(* Logix 5000 project; controller L32E vendor 1 type 14 code 77 rev 13.1; software revision 13.03 *)

TASK MainTask (continuous, watchdog 500 ms) : MainProgram

MODULES
   Controller : vendor 1 type 14 code 77 (CompactLogixL32EController 0, rev 13.1)
      LocalENB : 1769-L32E Ethernet Port (CompactLogixL32Ethernet 1, rev 13.1)
      Local : CompactBus (CompactVirtualAdapter 3, rev 13.1, Input RPI 2 ms)
         DPS : 1769-MODULE (Compact 1, rev 1.1, Output RPI 2 ms)   // 1769-DPS
END_MODULES

TYPE APP_CONSTANT_PATTERN :   // Constant Values Used for DPV1 Alarm and ExtDiagData
STRUCT
   UserAlarmData : SINT[32];   // Constants for Alarm Data
END_STRUCT
END_TYPE

TYPE APP_DPV1_PROG_CONTROL :   // Program Control Bits
STRUCT
   MainInitDone : BOOL;   // Main Initialization Complete
   Dpv1ReadRespInProgress : BOOL;   // DPV1 Read Response in Progress
   Dpv1WriteRespInProgress : BOOL;   // DPV1 Write Response in Progress
   Dpv1AlarmReqSend : BOOL;   // DPV1 Alarm Request Flag
   Dpv1AlarmReqInProgress : BOOL;   // DPV1 Alarm Request in Progress
   DpsDiagReqSend : BOOL;   // DPS Diagnostics Request Flag
   DpsDiagReqInProgress : BOOL;   // DPS Diagnostic Request in Progress
   Reserved0 : BOOL;   // Reserved
   Reserved1 : BOOL;   // Reserved
   Reserved2 : BOOL;   // Reserved
   Reserved3 : BOOL;   // Reserved
   Reserved4 : BOOL;   // Reserved
   Reserved5 : BOOL;   // Reserved
   Reserved6 : BOOL;   // Reserved
   Reserved7 : BOOL;   // Reserved
   Reserved8 : BOOL;   // Reserved
   DPV1RWIndCnt : SINT;   // DPV1 R/W Indication Counter
END_STRUCT
END_TYPE

TYPE APP_DPV1_STAT_COUNTER :   // DPV1 Status Counter
STRUCT
   NumReadWrite : DINT;   // Number of DPV1 Read Write Response Sent
   ReadRespPos : DINT;   // Number of DPV1 Read Response Successful
   ReadRespNeg : DINT;   // Number of DPV1 Read Response Failed
   WriteRespPos : DINT;   // Number of DPV1 Write Response Successful
   WriteRespNeg : DINT;   // Number of DPV1 Write Response Failed
   NumAlarmRequest : DINT;   // Number of DPV1 Alarm Requests sent
   AlarmRequestPos : DINT;   // Number of DPV1 Alarm Requests Successful
   AlarmRequestNeg : DINT;   // Number of DPV1 Alarm Requests Failed
   NumDiagReq : DINT;   // Number of Diagnostic Reports Sent
   DiagReqPos : DINT;   // Number of Diagnostic Report Successful
   DiagReqNeg : DINT;   // Number of Diagnostic Report Failed
END_STRUCT
END_TYPE

TYPE DPS_DEV_COMMAND_REGISTER :   // Device Command Register
STRUCT
   Reserved0 : BOOL;   // Reserved
   Reserved1 : BOOL;   // Reserved
   Reserved2 : BOOL;   // Reserved
   Reserved3 : BOOL;   // Reserved
   Reserved4 : BOOL;   // Reserved
   NRdy : BOOL;   // Application Not Ready
   Init : BOOL;   // Init ( Warm boot )
   Reset : BOOL;   // Reset ( Cold boot )
   Reserved5 : SINT;   // Reserved
   Reserved6 : SINT;   // Reserved
   ExtStaSelect : SINT;   // Extra Status Select
END_STRUCT
END_TYPE

TYPE DPS_DEV_STATUS_REGISTER :   // Device Status Register
STRUCT
   Reserved0 : BOOL;   // Reserved
   Reserved1 : BOOL;   // Reserved
   Reserved2 : BOOL;   // Reserved
   Reserved3 : BOOL;   // Reserved
   Reserved4 : BOOL;   // Reserved
   Com : BOOL;   // Communication
   Run : BOOL;   // Running
   Rdy : BOOL;   // Ready
   Reserved5 : SINT;   // Reserved
   Reserved6 : SINT;   // Reserved
   Reserved7 : SINT;   // Reserved
END_STRUCT
END_TYPE

TYPE DPS_DIAGNOSTIC_CONFIRM :   // DPS Diagnostics Confirmation
STRUCT
   Reserved1 : INT;   // Reserved
   Reserved2 : INT;   // Reserved
   Answer : SINT;   // Answer of Diag Req
   Failure : SINT;   // Failure
   Reserved4 : INT;   // Reserved
   Reserved5 : INT;   // Reserved
   Reserved6 : INT;   // Reserved
   Reserved7 : SINT;   // Reserved
   ExtDiagDataCnt : SINT;   // Extended Diagnostics Data Count
   Mode : SINT;   // Mode
   Function : SINT;   // Function
END_STRUCT
END_TYPE

TYPE DPS_DIAGNOSTIC_REQUEST :   // DPS Diagnostics Request
STRUCT
   Reserved1 : INT;   // Reserved
   Reserved2 : INT;   // Reserved
   Reserved3 : INT;   // Reserved
   Command : SINT;   // Command for Diag Req = 24
   Reserved4 : SINT;   // Reserved
   Reserved5 : INT;   // Reserved
   Reserved6 : INT;   // Reserved
   Reserved7 : SINT;   // Reserved
   ExtDiagDataCnt : SINT;   // Number of ext. diag data
   Mode : SINT;   // Diag mode: (0 = default, 1 = suppress Ext.DiagBit)
   Function : SINT;   // Send diag once (fix 18)
   DiagData : SINT[32];   // Extended diag data (format see PROFIBUS Norm)
END_STRUCT
END_TYPE

TYPE DPS_DPV1C1_ALARM_CONFIRM :   // DPV1 Alarm Confirmation
STRUCT
   Reserved1 : INT;   // Reserved
   Reserved2 : INT;   // Reserved
   Answer : SINT;   // DPV1 Alarm Answer Flag
   Failure : SINT;   // DPV1 Alarm Failure
   Reserved3 : INT;   // Reserved
   Reserved4 : INT;   // Reserved
   SlotNumber : INT;   // DPV1 Alarm Slot Number
   SequenceNumber : SINT;   // DPV1 Alarm Sequence Number
   DataCnt : SINT;   // DPV1 Alarm Data Count
   AlarmType : SINT;   // DPV1 Alarm Type
   Specifier : SINT;   // DPV1 Alarm Specifier
END_STRUCT
END_TYPE

TYPE DPS_DPV1C1_ALARM_REQUEST :   // DPV1 Alarm Request
STRUCT
   Reserved1 : INT;   // Reserved
   Reserved2 : INT;   // Reserved
   Reserved3 : INT;   // Reserved
   Command : SINT;   // DPV1 Alarm Command
   Reserved4 : SINT;   // Reserved
   Reserved5 : INT;   // Reserved
   SlotNumber : INT;   // DPV1 Alarm Slot Number
   SequenceNumber : SINT;   // DPV1 Alarm Sequence Number
   DataCnt : SINT;   // DPV1 Alarm Data Count
   AlarmType : SINT;   // DPV1 Alarm Type
   Specifier : SINT;   // DPV1 Alarm Specifier
   AlarmData : SINT[28];   // DPV1 Alarm Data Array
END_STRUCT
END_TYPE

TYPE DPS_DPV1C1_RW_INDICATION :   // DPV1 C1 Read/Write Indication
STRUCT
   ReadReq : BOOL;   // Indicates a Read request
   WriteReq : BOOL;   // Indicates a Write request
   Reserved2 : BOOL;   // Reserved
   Reserved3 : BOOL;   // Reserved
   Reserved4 : BOOL;   // Reserved
   Reserved5 : BOOL;   // Reserved
   Reserved6 : BOOL;   // Reserved
   Reserved7 : BOOL;   // Reserved
   RwCnt : SINT;   // ReadWrite indication counter
   MaAdr : SINT;   // Address of reqesting master
   Slot : SINT;   // Requested Slot Number
   Index : SINT;   // Requested Index
   DataLen : SINT;   // Requested Data Length
   Reserved8 : SINT;   // Reserved
   Reserved9 : SINT;   // Reserved
END_STRUCT
END_TYPE

TYPE DPS_DPV1C1_RW_RESP_CONFIRM :   // DPV1 Class 1 Read/Write Confirmation
STRUCT
   Reserved1 : INT;   // Reserved
   Reserved2 : INT;   // Reserved
   Answer : SINT;   // DPV1 R/W Answer
   Failure : SINT;   // DPV1 R/W Failure
   Reserved3 : INT;   // Reserved
   RwResp : SINT;   // Read Resp (=1) or Write Resp (=2)
   Reserved4 : SINT;   // Reserved
   MaAdr : SINT;   // Reply of reqesting Master Address
   Slot : SINT;   // Reply of requested Slot Number
   Index : SINT;   // Reply of requested Index
   DataLen : SINT;   // Number of requested data
   ErrCode1 : SINT;   // Reply of Error code 1 according to DPV1
   ErrCode2 : SINT;   // Reply of Error code 2 according to DPV1
   RWRespData : SINT[240];   // DPV1 Write data
END_STRUCT
END_TYPE

TYPE DPS_DPV1C1_RW_RESP_REQUEST :   // DPV1 Class 1 Read/Write Response Request
STRUCT
   Reserved1 : INT;   // Reserved
   Reserved2 : INT;   // Reserved
   Reserved3 : INT;   // Reserved
   Command : SINT;   // DPV1 ReadWrite Resp. Request (=17)
   Reserved4 : SINT;   // Reserved
   RwResp : SINT;   // Read Resp (=1) or Write Resp (=2)
   Reserved5 : SINT;   // Reserved
   MaAdr : SINT;   // Reply of reqesting Master Address
   Slot : SINT;   // Reply of requested Slot Number
   Index : SINT;   // Reply of requested Index
   DataLen : SINT;   // Reply of requested number of data
   ErrCode1 : SINT;   // Error code 1 according to DPV1
   ErrCode2 : SINT;   // Error code 2 according to DPV1
   RWRespData : SINT[240];   // DPV1 Read response data
END_STRUCT
END_TYPE

TYPE DPS_FW_REVISION :   // Firmware Major/Minor Revision
STRUCT
   FwMinor : SINT;   // Firmware Minor Revison
   FwMajor : SINT;   // Firmware Major Revison
   Reserved : INT;   // Reserved
END_STRUCT
END_TYPE

TYPE DPS_INPUT_ARRAY :   // DPS Input Array
STRUCT
   DevStaReg : DPS_DEV_STATUS_REGISTER;   // Device Status Registers
   FwRev : DPS_FW_REVISION;   // Firmware Revision
   StaField : DPS_STATUS_FIELD;   // DPS Status Registers
   PBOutputData : SINT[380];   // PROFIBUS Output Data from Matser
END_STRUCT
END_TYPE

TYPE DPS_OUTPUT_ARRAY :   // DPS Output Array
STRUCT
   DevCmdReg : DPS_DEV_COMMAND_REGISTER;   // Device Command Register
   PBInputData : SINT[244];   // PROFIBIBUS Input Data for Master
END_STRUCT
END_TYPE

TYPE DPS_STATUS_FIELD :   // DPS Status Field
STRUCT
   ExtStaSelect : INT;   // Extended Status Select
   ExtStaLen : INT;   // Extended Status Length
   Baudrate : INT;   // Slave Baudrate
   Busaddress : SINT;   // Slave Bus Address
   UserFlags : SINT;   // User Flags
   Ident : INT;   // Slave Ident Number
   TaskState : INT;   // Slave Task State
   InputDataLen : INT;   // Slave Input Data Length
   OutputDataLen : INT;   // Slave Output Data Length
   ErrorCount : INT;   // Slave Error Count
   LastError : SINT;   // Slave Last Error
   Pad : SINT;   // Reserved
   WatchdogTime : INT;   // Slave Watchdog Time
   IrqCounter : INT;   // Slave Interrupt Counter
   C1Ind : DPS_DPV1C1_RW_INDICATION;   // DPV1 Class 1 Indication Registers
   ExtStatusInfo : SINT[96];   // Extened Status Information
END_STRUCT
END_TYPE

VAR_GLOBAL   (* controller tags *)
   AppConstPattern : APP_CONSTANT_PATTERN := (UserAlarmData[0] := 'M', UserAlarmData[1] := 'A', UserAlarmData[2] := 'Y', UserAlarmData[3] := 'D', UserAlarmData[4] := 'A', UserAlarmData[5] := 'Y', UserAlarmData[6] := ',', UserAlarmData[7] := ' ', UserAlarmData[8] := 'M', UserAlarmData[9] := 'A', UserAlarmData[10] := 'Y', UserAlarmData[11] := 'D', UserAlarmData[12] := 'A', UserAlarmData[13] := 'Y');
   AppCtrl : APP_DPV1_PROG_CONTROL;
   AppStatCnt : APP_DPV1_STAT_COUNTER;
   DiagCnf : DPS_DIAGNOSTIC_CONFIRM;
   DiagReq : DPS_DIAGNOSTIC_REQUEST;
   DiagReqMsg : MESSAGE;
        MessageParameters(ServiceCode := 16#0064, LocalElement := DiagReq, DestinationTag := DiagCnf, ...)
   DpsInputArray : DPS_INPUT_ARRAY;
   DpsOutputArray : DPS_OUTPUT_ARRAY;
   Dpv1AlarmCnf : DPS_DPV1C1_ALARM_CONFIRM;
   Dpv1AlarmMsg : MESSAGE;
        MessageParameters(ServiceCode := 16#0064, LocalElement := Dpv1AlarmReq, DestinationTag := Dpv1AlarmCnf, ...)
   Dpv1AlarmReq : DPS_DPV1C1_ALARM_REQUEST := (DataCnt := 15);
   DPV1RWDataBuffer : SINT[240];   // Buffer for DPV1 Data
   Dpv1RWMsg : MESSAGE;
        MessageParameters(ServiceCode := 16#0064, LocalElement := Dpv1RWRespReq, DestinationTag := Dpv1RWRespCnf, ...)
   Dpv1RWRespCnf : DPS_DPV1C1_RW_RESP_CONFIRM;
   Dpv1RWRespReq : DPS_DPV1C1_RW_RESP_REQUEST;
END_VAR

PROGRAM MainProgram   (* routine attr 65 MainRoutine *)

ROUTINE Diagnostic_Req   (* ladder *)
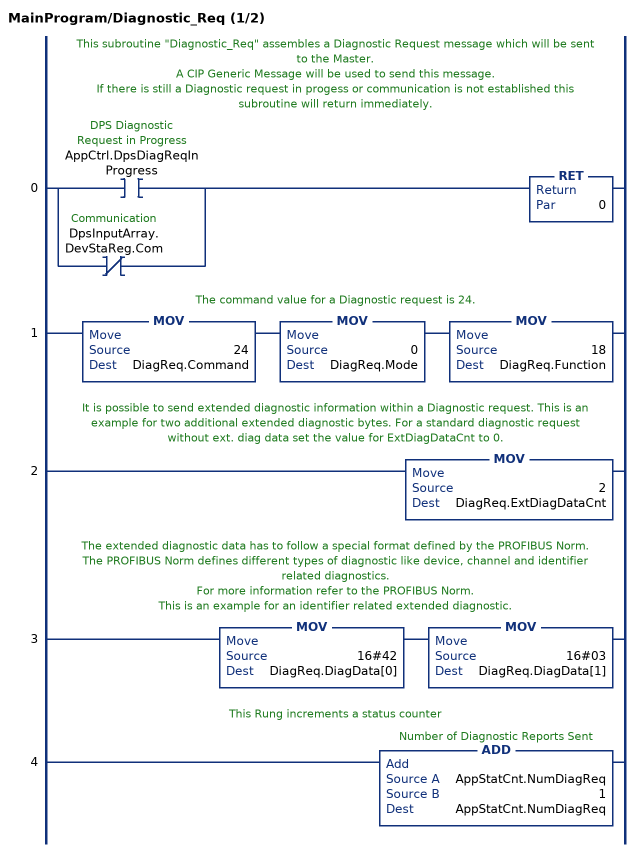
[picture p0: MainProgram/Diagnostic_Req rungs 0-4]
   // This subroutine "Diagnostic_Req" assembles a Diagnostic Request message which will be sent to the Master.
   // A CIP Generic Message will be used to send this message.
   // If there is still a Diagnostic request in progess or communication is not established this subroutine will return immediately.
   0: [XIC(AppCtrl.DpsDiagReqInProgress) ,XIO(DpsInputArray.DevStaReg.Com) ]RET(0);
   // The command value for a Diagnostic request is 24.
   1: MOV(24,DiagReq.Command)MOV(0,DiagReq.Mode)MOV(18,DiagReq.Function);
   // It is possible to send extended diagnostic information within a Diagnostic request. This is an example for two additional extended diagnostic bytes. For a standard diagnostic request without ext. diag data set the value for ExtDiagDataCnt to 0.
   2: MOV(2,DiagReq.ExtDiagDataCnt);
   // The extended diagnostic data has to follow a special format defined by the PROFIBUS Norm. The PROFIBUS Norm defines different types of diagnostic like device, channel and identifier related diagnostics.
   // For more information refer to the PROFIBUS Norm.
   // This is an example for an identifier related extended diagnostic.
   3: MOV(16#42,DiagReq.DiagData[0])MOV(16#03,DiagReq.DiagData[1]);
   // This Rung increments a status counter
   4: ADD(AppStatCnt.NumDiagReq,1,AppStatCnt.NumDiagReq);
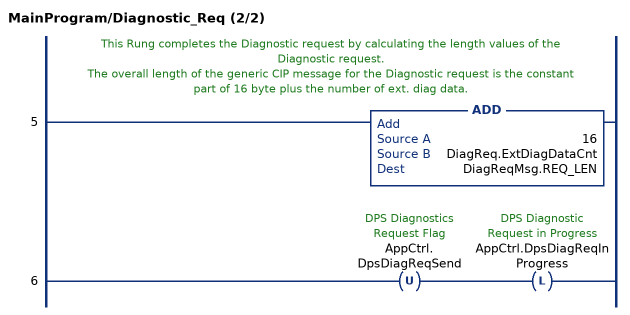
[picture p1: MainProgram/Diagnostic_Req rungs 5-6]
   // This Rung completes the Diagnostic request by calculating the length values of the Diagnostic request.
   // The overall length of the generic CIP message for the Diagnostic request is the constant part of 16 byte plus the number of ext. diag data.
   5: ADD(16,DiagReq.ExtDiagDataCnt,DiagReqMsg.REQ_LEN);
   6: OTU(AppCtrl.DpsDiagReqSend)OTL(AppCtrl.DpsDiagReqInProgress);
END_ROUTINE

ROUTINE Diagnostic_Req_Progress   (* ladder *)
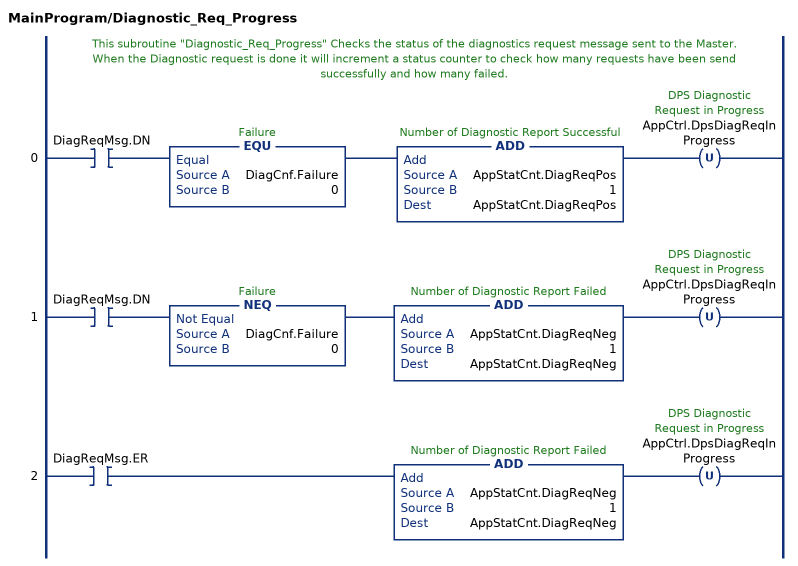
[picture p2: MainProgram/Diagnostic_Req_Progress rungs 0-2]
   // This subroutine "Diagnostic_Req_Progress" Checks the status of the diagnostics request message sent to the Master.
   // When the Diagnostic request is done it will increment a status counter to check how many requests have been send successfully and how many failed.
   0: XIC(DiagReqMsg.DN)EQU(DiagCnf.Failure,0)ADD(AppStatCnt.DiagReqPos,1,AppStatCnt.DiagReqPos)OTU(AppCtrl.DpsDiagReqInProgress);
   1: XIC(DiagReqMsg.DN)NEQ(DiagCnf.Failure,0)ADD(AppStatCnt.DiagReqNeg,1,AppStatCnt.DiagReqNeg)OTU(AppCtrl.DpsDiagReqInProgress);
   2: XIC(DiagReqMsg.ER)ADD(AppStatCnt.DiagReqNeg,1,AppStatCnt.DiagReqNeg)OTU(AppCtrl.DpsDiagReqInProgress);
END_ROUTINE

ROUTINE DPV1C1_Alarm_Req   (* ladder *)
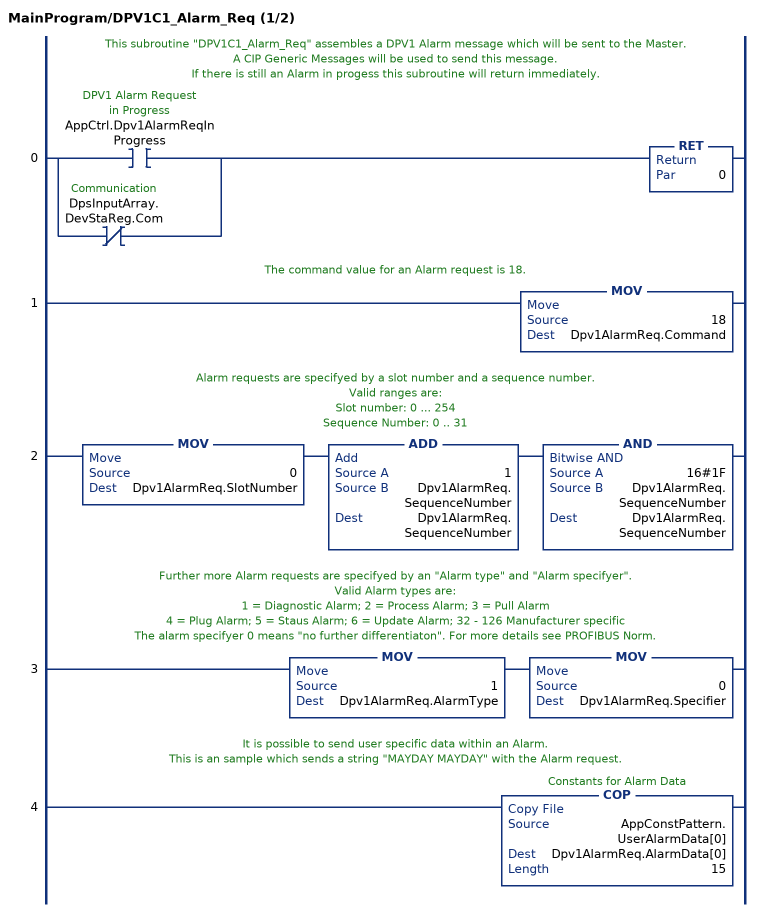
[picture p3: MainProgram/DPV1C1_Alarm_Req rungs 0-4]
   // This subroutine "DPV1C1_Alarm_Req" assembles a DPV1 Alarm message which will be sent to the Master.
   // A CIP Generic Messages will be used to send this message.
   // If there is still an Alarm in progess this subroutine will return immediately.
   0: [XIC(AppCtrl.Dpv1AlarmReqInProgress) ,XIO(DpsInputArray.DevStaReg.Com) ]RET(0);
   // The command value for an Alarm request is 18.
   1: MOV(18,Dpv1AlarmReq.Command);
   // Alarm requests are specifyed by a slot number and a sequence number.
   // Valid ranges are:
   // Slot number: 0 ... 254
   // Sequence Number: 0 .. 31
   2: MOV(0,Dpv1AlarmReq.SlotNumber)ADD(1,Dpv1AlarmReq.SequenceNumber,Dpv1AlarmReq.SequenceNumber)AND(16#1F,Dpv1AlarmReq.SequenceNumber,Dpv1AlarmReq.SequenceNumber);
   // Further more Alarm requests are specifyed by an "Alarm type" and "Alarm specifyer".
   // Valid Alarm types are:
   // 1 = Diagnostic Alarm; 2 = Process Alarm; 3 = Pull Alarm
   // 4 = Plug Alarm; 5 = Staus Alarm; 6 = Update Alarm; 32 - 126 Manufacturer specific
   // The alarm specifyer 0 means "no further differentiaton". For more details see PROFIBUS Norm.
   3: MOV(1,Dpv1AlarmReq.AlarmType)MOV(0,Dpv1AlarmReq.Specifier);
   // It is possible to send user specific data within an Alarm.
   // This is an sample which sends a string "MAYDAY MAYDAY" with the Alarm request.
   4: COP(AppConstPattern.UserAlarmData[0],Dpv1AlarmReq.AlarmData[0],15);
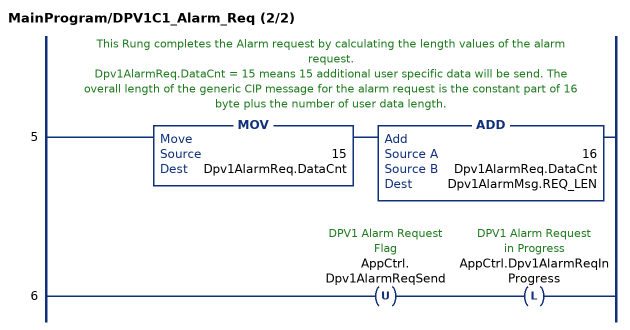
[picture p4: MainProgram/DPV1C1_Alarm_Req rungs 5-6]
   // This Rung completes the Alarm request by calculating the length values of the alarm request.
   // Dpv1AlarmReq.DataCnt = 15 means 15 additional user specific data will be send. The overall length of the generic CIP message for the alarm request is the constant part of 16 byte plus the number of user data length.
   5: MOV(15,Dpv1AlarmReq.DataCnt)ADD(16,Dpv1AlarmReq.DataCnt,Dpv1AlarmMsg.REQ_LEN);
   6: OTU(AppCtrl.Dpv1AlarmReqSend)OTL(AppCtrl.Dpv1AlarmReqInProgress);
END_ROUTINE

ROUTINE DPV1C1_Alarm_Req_Progress   (* ladder *)
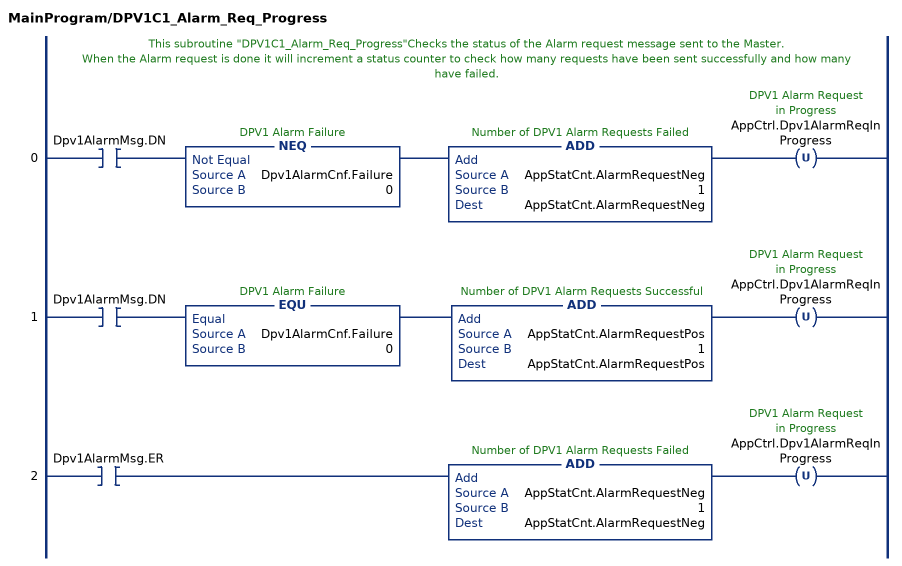
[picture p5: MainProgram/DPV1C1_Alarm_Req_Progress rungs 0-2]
   // This subroutine "DPV1C1_Alarm_Req_Progress"Checks the status of the Alarm request message sent to the Master.
   // When the Alarm request is done it will increment a status counter to check how many requests have been sent successfully and how many have failed.
   0: XIC(Dpv1AlarmMsg.DN)NEQ(Dpv1AlarmCnf.Failure,0)ADD(AppStatCnt.AlarmRequestNeg,1,AppStatCnt.AlarmRequestNeg)OTU(AppCtrl.Dpv1AlarmReqInProgress);
   1: XIC(Dpv1AlarmMsg.DN)EQU(Dpv1AlarmCnf.Failure,0)ADD(AppStatCnt.AlarmRequestPos,1,AppStatCnt.AlarmRequestPos)OTU(AppCtrl.Dpv1AlarmReqInProgress);
   2: XIC(Dpv1AlarmMsg.ER)ADD(AppStatCnt.AlarmRequestNeg,1,AppStatCnt.AlarmRequestNeg)OTU(AppCtrl.Dpv1AlarmReqInProgress);
END_ROUTINE

ROUTINE DPV1C1_Progress   (* ladder *)
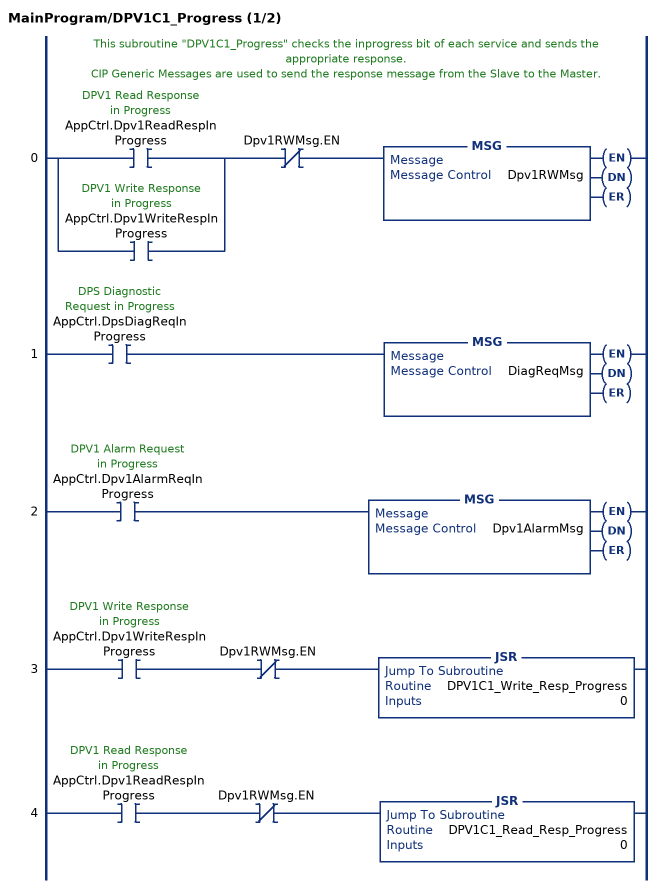
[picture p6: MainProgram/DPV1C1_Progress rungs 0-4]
   // This subroutine "DPV1C1_Progress" checks the inprogress bit of each service and sends the appropriate response.
   // CIP Generic Messages are used to send the response message from the Slave to the Master.
   0: [XIC(AppCtrl.Dpv1ReadRespInProgress) ,XIC(AppCtrl.Dpv1WriteRespInProgress) ]XIO(Dpv1RWMsg.EN)MSG(Dpv1RWMsg);
   1: XIC(AppCtrl.DpsDiagReqInProgress)MSG(DiagReqMsg);
   2: XIC(AppCtrl.Dpv1AlarmReqInProgress)MSG(Dpv1AlarmMsg);
   3: XIC(AppCtrl.Dpv1WriteRespInProgress)XIO(Dpv1RWMsg.EN)JSR(DPV1C1_Write_Resp_Progress,0);
   4: XIC(AppCtrl.Dpv1ReadRespInProgress)XIO(Dpv1RWMsg.EN)JSR(DPV1C1_Read_Resp_Progress,0);
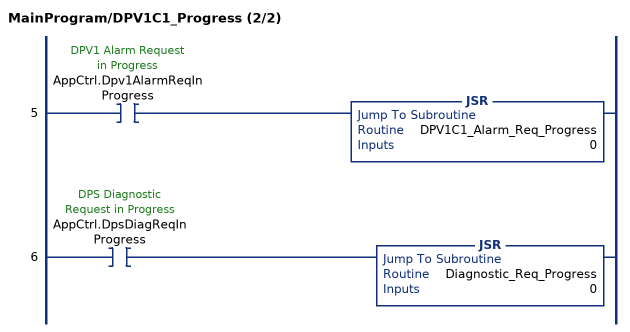
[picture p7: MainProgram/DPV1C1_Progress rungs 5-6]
   5: XIC(AppCtrl.Dpv1AlarmReqInProgress)JSR(DPV1C1_Alarm_Req_Progress,0);
   6: XIC(AppCtrl.DpsDiagReqInProgress)JSR(Diagnostic_Req_Progress,0);
END_ROUTINE

ROUTINE DPV1C1_Read_Resp   (* ladder *)
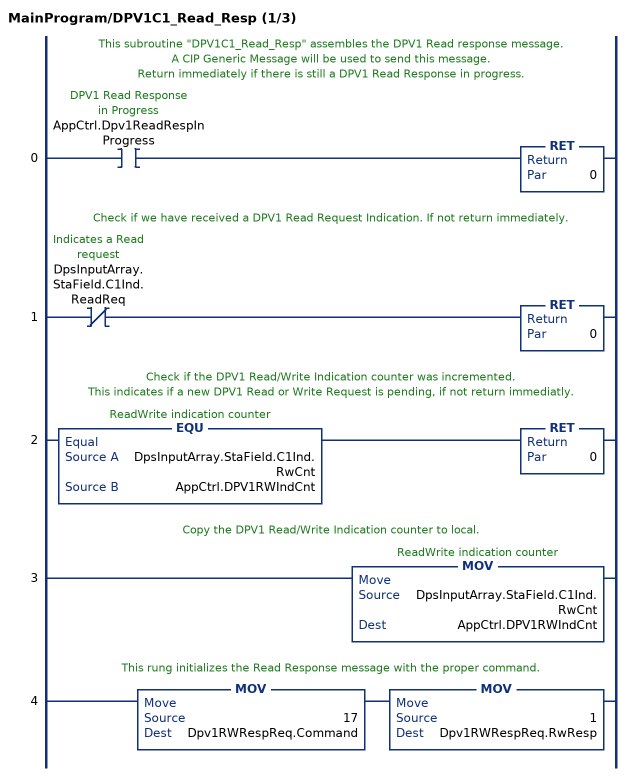
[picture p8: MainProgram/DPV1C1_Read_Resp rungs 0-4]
   // This subroutine "DPV1C1_Read_Resp" assembles the DPV1 Read response message.
   // A CIP Generic Message will be used to send this message.
   // Return immediately if there is still a DPV1 Read Response in progress.
   0: XIC(AppCtrl.Dpv1ReadRespInProgress)RET(0);
   // Check if we have received a DPV1 Read Request Indication. If not return immediately.
   1: XIO(DpsInputArray.StaField.C1Ind.ReadReq)RET(0);
   // Check if the DPV1 Read/Write Indication counter was incremented.
   // This indicates if a new DPV1 Read or Write Request is pending, if not return immediatly.
   2: EQU(DpsInputArray.StaField.C1Ind.RwCnt,AppCtrl.DPV1RWIndCnt)RET(0);
   // Copy the DPV1 Read/Write Indication counter to local.
   3: MOV(DpsInputArray.StaField.C1Ind.RwCnt,AppCtrl.DPV1RWIndCnt);
   // This rung initializes the Read Response message with the proper command.
   4: MOV(17,Dpv1RWRespReq.Command)MOV(1,Dpv1RWRespReq.RwResp);
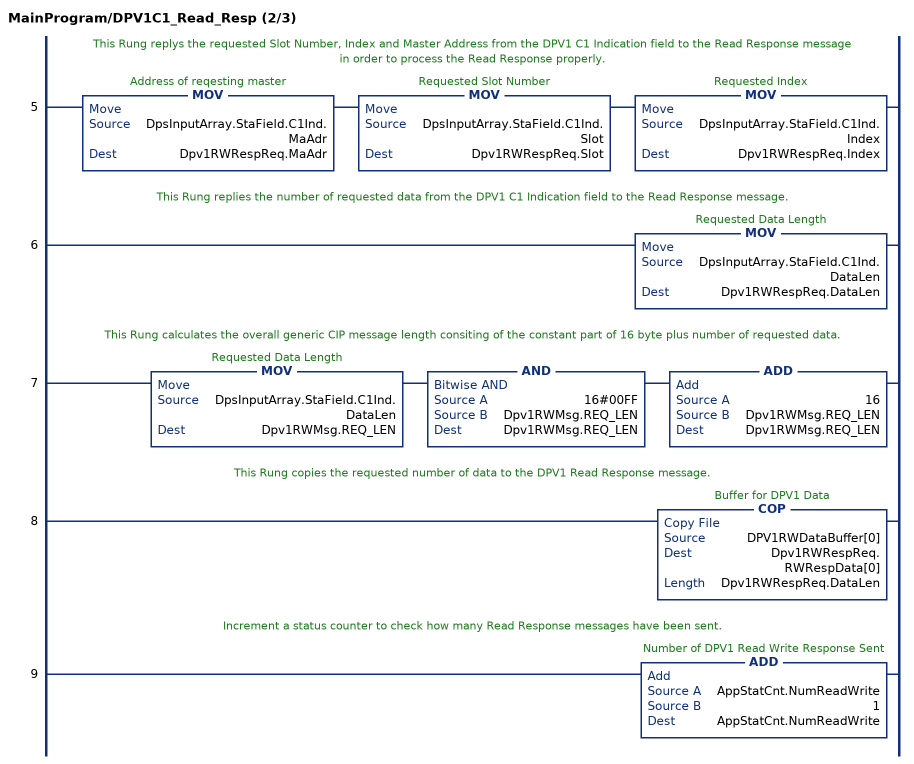
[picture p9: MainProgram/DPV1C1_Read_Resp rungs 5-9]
   // This Rung replys the requested Slot Number, Index and Master Address from the DPV1 C1 Indication field to the Read Response message
   // in order to process the Read Response properly.
   5: MOV(DpsInputArray.StaField.C1Ind.MaAdr,Dpv1RWRespReq.MaAdr)MOV(DpsInputArray.StaField.C1Ind.Slot,Dpv1RWRespReq.Slot)MOV(DpsInputArray.StaField.C1Ind.Index,Dpv1RWRespReq.Index);
   // This Rung replies the number of requested data from the DPV1 C1 Indication field to the Read Response message.
   6: MOV(DpsInputArray.StaField.C1Ind.DataLen,Dpv1RWRespReq.DataLen);
   // This Rung calculates the overall generic CIP message length consiting of the constant part of 16 byte plus number of requested data.
   7: MOV(DpsInputArray.StaField.C1Ind.DataLen,Dpv1RWMsg.REQ_LEN)AND(16#00FF,Dpv1RWMsg.REQ_LEN,Dpv1RWMsg.REQ_LEN)ADD(16,Dpv1RWMsg.REQ_LEN,Dpv1RWMsg.REQ_LEN);
   // This Rung copies the requested number of data to the DPV1 Read Response message.
   8: COP(DPV1RWDataBuffer[0],Dpv1RWRespReq.RWRespData[0],Dpv1RWRespReq.DataLen);
   // Increment a status counter to check how many Read Response messages have been sent.
   9: ADD(AppStatCnt.NumReadWrite,1,AppStatCnt.NumReadWrite);
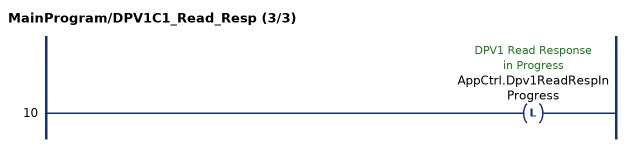
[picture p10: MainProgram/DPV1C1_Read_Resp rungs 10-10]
   10: OTL(AppCtrl.Dpv1ReadRespInProgress);
END_ROUTINE

ROUTINE DPV1C1_Read_Resp_Progress   (* ladder *)
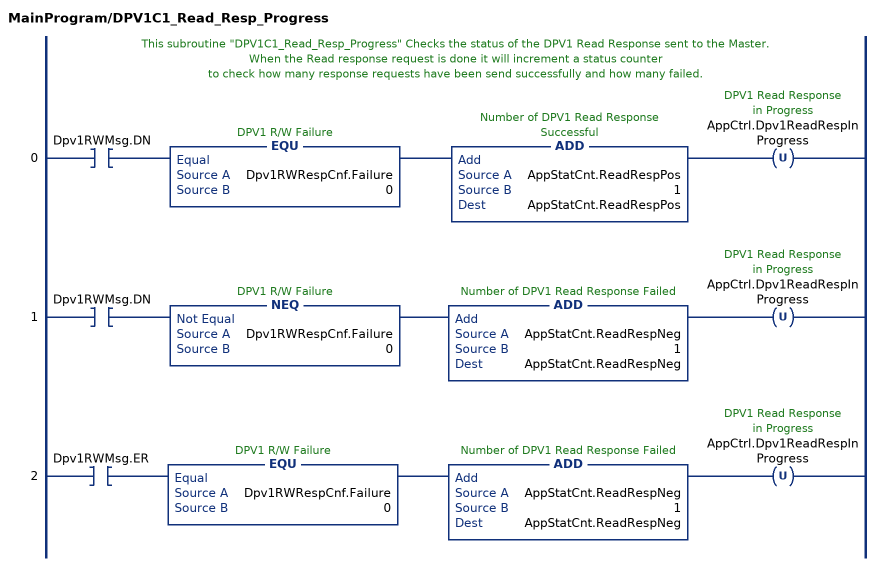
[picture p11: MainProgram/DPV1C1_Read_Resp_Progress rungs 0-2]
   // This subroutine "DPV1C1_Read_Resp_Progress" Checks the status of the DPV1 Read Response sent to the Master.
   // When the Read response request is done it will increment a status counter
   // to check how many response requests have been send successfully and how many failed.
   0: XIC(Dpv1RWMsg.DN)EQU(Dpv1RWRespCnf.Failure,0)ADD(AppStatCnt.ReadRespPos,1,AppStatCnt.ReadRespPos)OTU(AppCtrl.Dpv1ReadRespInProgress);
   1: XIC(Dpv1RWMsg.DN)NEQ(Dpv1RWRespCnf.Failure,0)ADD(AppStatCnt.ReadRespNeg,1,AppStatCnt.ReadRespNeg)OTU(AppCtrl.Dpv1ReadRespInProgress);
   2: XIC(Dpv1RWMsg.ER)EQU(Dpv1RWRespCnf.Failure,0)ADD(AppStatCnt.ReadRespNeg,1,AppStatCnt.ReadRespNeg)OTU(AppCtrl.Dpv1ReadRespInProgress);
END_ROUTINE

ROUTINE DPV1C1_Write_Resp   (* ladder *)
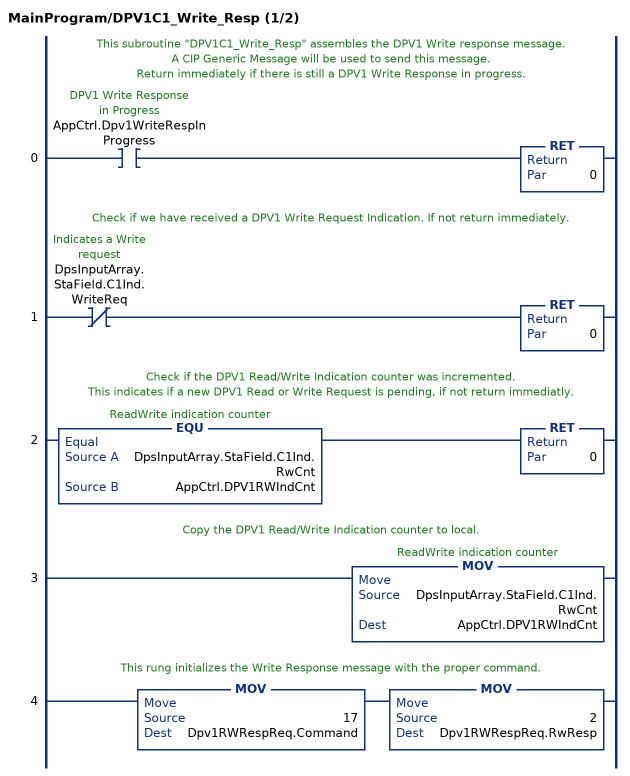
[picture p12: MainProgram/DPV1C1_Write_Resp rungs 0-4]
   // This subroutine "DPV1C1_Write_Resp" assembles the DPV1 Write response message.
   // A CIP Generic Message will be used to send this message.
   // Return immediately if there is still a DPV1 Write Response in progress.
   0: XIC(AppCtrl.Dpv1WriteRespInProgress)RET(0);
   // Check if we have received a DPV1 Write Request Indication. If not return immediately.
   1: XIO(DpsInputArray.StaField.C1Ind.WriteReq)RET(0);
   // Check if the DPV1 Read/Write Indication counter was incremented.
   // This indicates if a new DPV1 Read or Write Request is pending, if not return immediatly.
   2: EQU(DpsInputArray.StaField.C1Ind.RwCnt,AppCtrl.DPV1RWIndCnt)RET(0);
   // Copy the DPV1 Read/Write Indication counter to local.
   3: MOV(DpsInputArray.StaField.C1Ind.RwCnt,AppCtrl.DPV1RWIndCnt);
   // This rung initializes the Write Response message with the proper command.
   4: MOV(17,Dpv1RWRespReq.Command)MOV(2,Dpv1RWRespReq.RwResp);
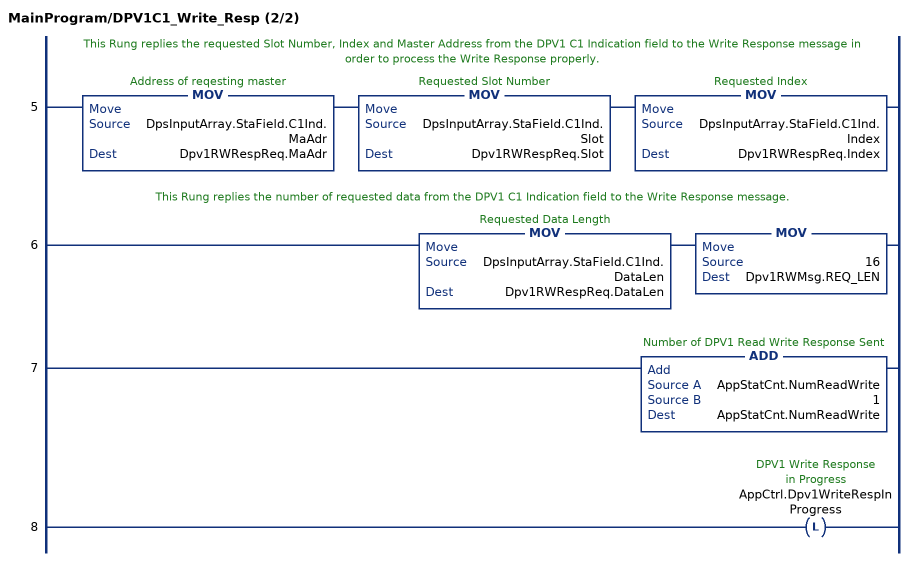
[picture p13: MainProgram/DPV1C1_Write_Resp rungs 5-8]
   // This Rung replies the requested Slot Number, Index and Master Address from the DPV1 C1 Indication field to the Write Response message in order to process the Write Response properly.
   5: MOV(DpsInputArray.StaField.C1Ind.MaAdr,Dpv1RWRespReq.MaAdr)MOV(DpsInputArray.StaField.C1Ind.Slot,Dpv1RWRespReq.Slot)MOV(DpsInputArray.StaField.C1Ind.Index,Dpv1RWRespReq.Index);
   // This Rung replies the number of requested data from the DPV1 C1 Indication field to the Write Response message.
   6: MOV(DpsInputArray.StaField.C1Ind.DataLen,Dpv1RWRespReq.DataLen)MOV(16,Dpv1RWMsg.REQ_LEN);
   7: ADD(AppStatCnt.NumReadWrite,1,AppStatCnt.NumReadWrite);
   8: OTL(AppCtrl.Dpv1WriteRespInProgress);
END_ROUTINE

ROUTINE DPV1C1_Write_Resp_Progress   (* ladder *)
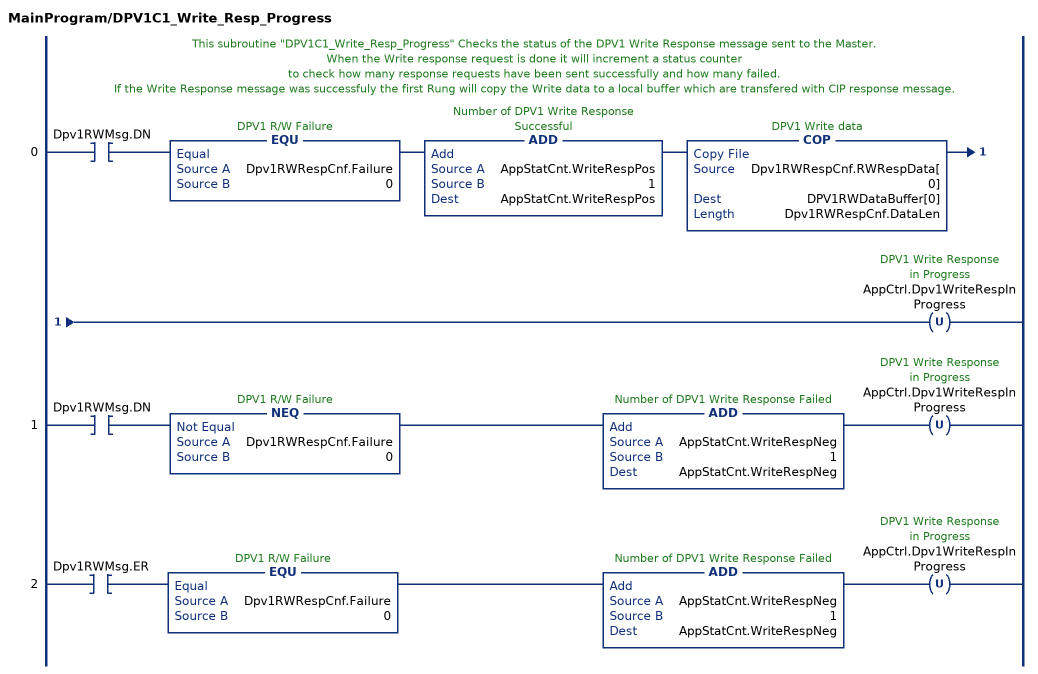
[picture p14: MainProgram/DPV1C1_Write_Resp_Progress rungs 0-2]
   // This subroutine "DPV1C1_Write_Resp_Progress" Checks the status of the DPV1 Write Response message sent to the Master.
   // When the Write response request is done it will increment a status counter
   // to check how many response requests have been sent successfully and how many failed.
   // If the Write Response message was successfuly the first Rung will copy the Write data to a local buffer which are transfered with CIP response message.
   0: XIC(Dpv1RWMsg.DN)EQU(Dpv1RWRespCnf.Failure,0)ADD(AppStatCnt.WriteRespPos,1,AppStatCnt.WriteRespPos)COP(Dpv1RWRespCnf.RWRespData[0],DPV1RWDataBuffer[0],Dpv1RWRespCnf.DataLen)OTU(AppCtrl.Dpv1WriteRespInProgress);
   1: XIC(Dpv1RWMsg.DN)NEQ(Dpv1RWRespCnf.Failure,0)ADD(AppStatCnt.WriteRespNeg,1,AppStatCnt.WriteRespNeg)OTU(AppCtrl.Dpv1WriteRespInProgress);
   2: XIC(Dpv1RWMsg.ER)EQU(Dpv1RWRespCnf.Failure,0)ADD(AppStatCnt.WriteRespNeg,1,AppStatCnt.WriteRespNeg)OTU(AppCtrl.Dpv1WriteRespInProgress);
END_ROUTINE

ROUTINE MainRoutine   (* ladder *)
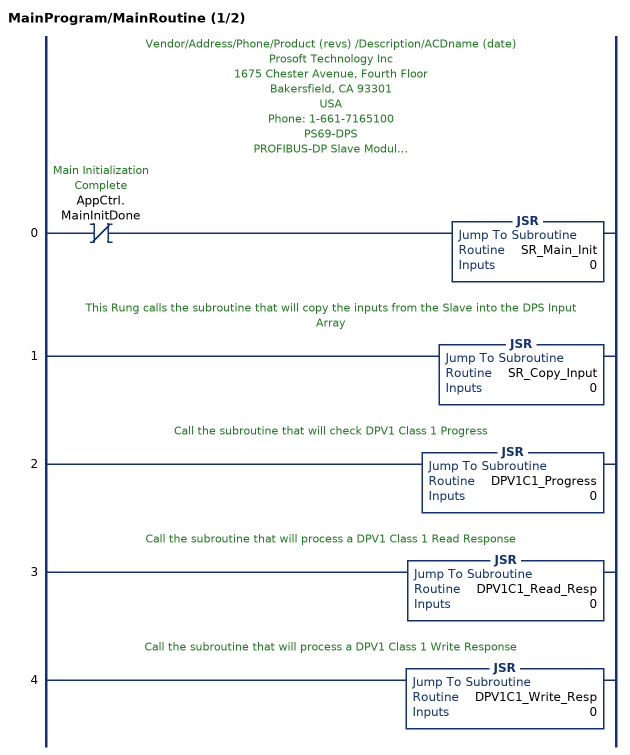
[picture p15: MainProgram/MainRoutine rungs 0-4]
   // Vendor/Address/Phone/Product (revs) /Description/ACDname (date)
   // Prosoft Technology Inc
   // 1675 Chester Avenue, Fourth Floor
   // Bakersfield, CA 93301
   // USA
   // Phone: 1-661-7165100
   // PS69-DPS
   // PROFIBUS-DP Slave Module
   // PS69_DPS_messaging_L32E.ACD (Rev1.0) (07/28/05)
   // Although this program has been developed with great care and intensively tested,
   // Prosoft Technology Inc cannot guarantee the suitability of this program
   // for any purpose not confirmed by us in writing.
   // We reserve the right to modify our products and their specifications at any time in as far as this contributes to technical progress.
   // The version of the manual supplied with the program applies.
   // This program is a basic example RSLogix5000 project used for sending PROFIBUS messages to the communication module "PS69-DPS". This project provides an example for every supported PROFIBUS message by the module.
   // For detailed information about the these messages (functionality, parameters, error codes etc. ) refer to the module User Manual document.
   // This Rung calls all init routines for one time, to initialize the PROFIBUS commands.
   0: XIO(AppCtrl.MainInitDone)JSR(SR_Main_Init,0);
   // This Rung calls the subroutine that will copy the inputs from the Slave into the DPS Input Array
   1: JSR(SR_Copy_Input,0);
   // Call the subroutine that will check DPV1 Class 1 Progress
   2: JSR(DPV1C1_Progress,0);
   // Call the subroutine that will process a DPV1 Class 1 Read Response
   3: JSR(DPV1C1_Read_Resp,0);
   // Call the subroutine that will process a DPV1 Class 1 Write Response
   4: JSR(DPV1C1_Write_Resp,0);
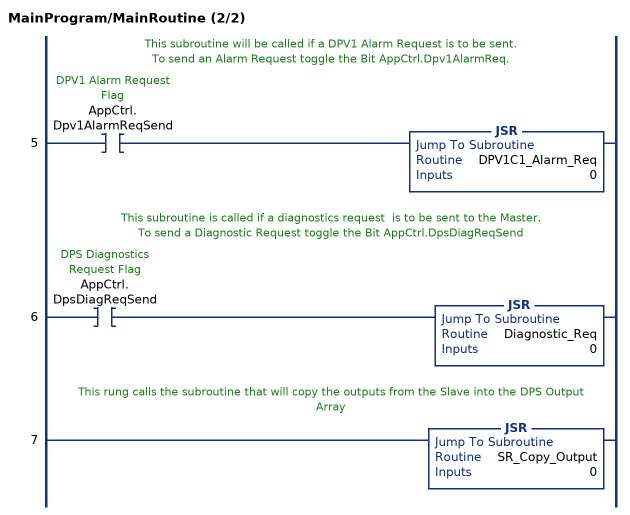
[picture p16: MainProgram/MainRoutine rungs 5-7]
   // This subroutine will be called if a DPV1 Alarm Request is to be sent.
   // To send an Alarm Request toggle the Bit AppCtrl.Dpv1AlarmReq.
   5: XIC(AppCtrl.Dpv1AlarmReqSend)JSR(DPV1C1_Alarm_Req,0);
   // This subroutine is called if a diagnostics request  is to be sent to the Master.
   // To send a Diagnostic Request toggle the Bit AppCtrl.DpsDiagReqSend
   6: XIC(AppCtrl.DpsDiagReqSend)JSR(Diagnostic_Req,0);
   // This rung calls the subroutine that will copy the outputs from the Slave into the DPS Output Array
   7: JSR(SR_Copy_Output,0);
END_ROUTINE

ROUTINE SR_Copy_Input   (* ladder *)
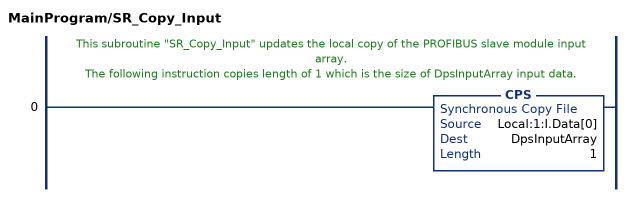
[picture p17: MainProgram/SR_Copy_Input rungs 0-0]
   // This subroutine "SR_Copy_Input" updates the local copy of the PROFIBUS slave module input array.
   // The following instruction copies length of 1 which is the size of DpsInputArray input data.
   0: CPS(Local:1:I.Data[0],DpsInputArray,1);
END_ROUTINE

ROUTINE SR_Copy_Output   (* ladder *)
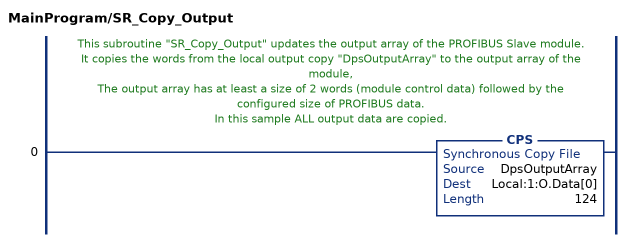
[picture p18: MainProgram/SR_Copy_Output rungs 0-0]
   // This subroutine "SR_Copy_Output" updates the output array of the PROFIBUS Slave module.
   // It copies the words from the local output copy "DpsOutputArray" to the output array of the module,
   // The output array has at least a size of 2 words (module control data) followed by the configured size of PROFIBUS data.
   // In this sample ALL output data are copied.
   0: CPS(DpsOutputArray,Local:1:O.Data[0],124);
END_ROUTINE

ROUTINE SR_Main_Init   (* ladder *)
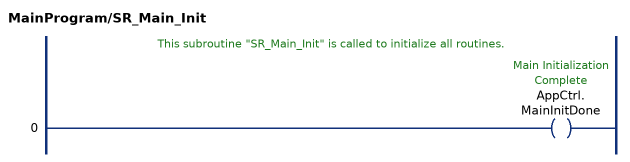
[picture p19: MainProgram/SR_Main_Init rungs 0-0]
   // This subroutine "SR_Main_Init" is called to initialize all routines.
   0: OTE(AppCtrl.MainInitDone);
END_ROUTINE
END_PROGRAM
